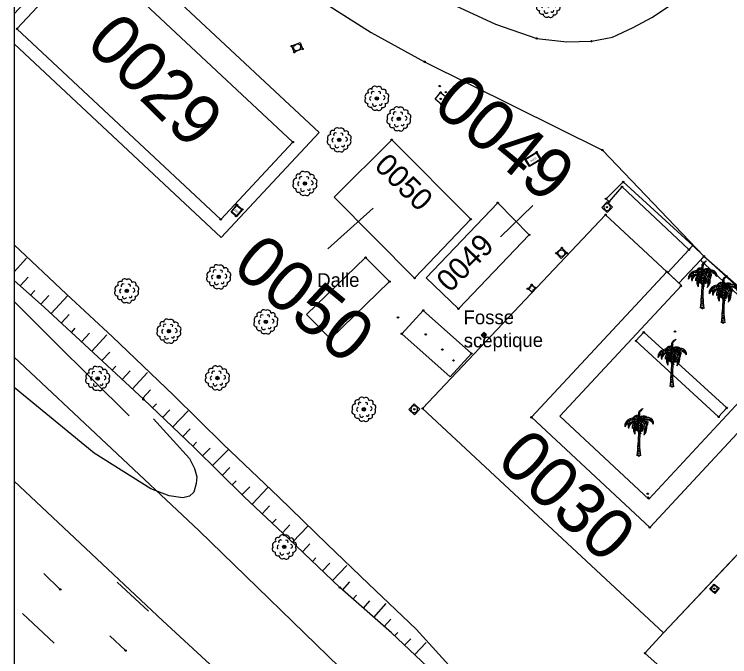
# Model space of a CAD drawing. Extents: x 344013 to 344423, y 298505 to 298795.
# Drawn here: x 344012.9 to 344064.6, y 298644.7 to 298691.1 of the extents above; entities that cross this region are included whole.
import ezdxf

# ---------------------------------------------------------------- set-up
doc = ezdxf.new("R2010")
doc.units = 0
for name, color, linetype in [('Default', 7, 'Continuous'), ('DH_CADRE -CARTOUCHE', 7, 'Continuous'), ('IMM_VOIRIE VOIE FERREE', 7, 'Continuous'), ('PC_CONCRETE', 7, 'Continuous'), ('PS_BOLT', 7, 'Continuous'), ('PS_CONST', 7, 'Continuous'), ('PS_HIDDEN', 7, 'Continuous'), ('PS_WELD', 7, 'Continuous'), ('RES_ELECTRICITE', 7, 'Continuous'), ('TOPO_COURBE NIVEAU', 7, 'Continuous'), ('TOPO_POINT', 7, 'Continuous'), ('TOPO_TALUS-TERRAIN NATUREL', 7, 'Continuous'), ('VOIRIE_BORDURE', 7, 'Continuous'), ('VOIRIE_ESPACE VERT', 7, 'Continuous')]:
    doc.layers.add(name, color=color, linetype=linetype)

# ---------------------------------------------------------------- blocks, each defined once
blk = doc.blocks.new('REG_INC')
at = {"layer": 'Default'}
for p, q in [((0, 1), (1, 1)), ((0, 0), (0, 1)), ((1, 1), (1, 0)), ((1, 0), (0, 0))]:
    blk.add_line(p, q, dxfattribs=at)
for centre, start, end in [((0.498, 0.5), 135.00554, 180.00554), ((0.5, 0.498), 90.00577, 135.00577), ((0.5, 0.5), 45.00687, 90.00687), ((0.499, 0.499), 0.00663, 45.00663), ((0.501, 0.5), 180.00663, 225.00663), ((0.499, 0.498), 225.00686, 270.00686), ((0.499, 0.5), 270.00577, 315.00577), ((0.501, 0.499), 315.00554, 0.00554)]:
    blk.add_arc(centre, 0.44, start, end, dxfattribs=at)
blk = doc.blocks.new('RES_ELECTRICITE')
at = {"layer": 'RES_ELECTRICITE'}
for points in [[(0, 0), (0, 1), (1, 1), (1, 0)], [(0.05, 0.05), (0.05, 0.95), (0.95, 0.95), (0.95, 0.05)]]:
    blk.add_lwpolyline(points, close=True, dxfattribs=at)
blk.add_text('EEC', height=0.2, dxfattribs=at).set_placement((0.237, 0.46))
blk = doc.blocks.new('POINT_DISPLAY')
at = {"layer": 'Default'}
blk.add_circle((0, 0), 0.05, dxfattribs=at)
blk = doc.blocks.new('COCO')
at = {"layer": 'Default'}
for p, q in [((-0.037, 1.06), (0.056, 1.071)), ((0.058, 1.14), (-0.03, 1.162)), ((-0.026, 1.226), (0.061, 1.212)), ((-0.062, 0.537), (0.046, 0.552)), ((0.047, 0.655), (-0.058, 0.642)), ((-0.046, 0.891), (0.052, 0.927)), ((0.054, 0.998), (-0.041, 0.985)), ((0.046, 0.033), (-0.076, 0.051)), ((-0.073, 0.17), (0.045, 0.209)), ((0.045, 0.292), (-0.07, 0.288)), ((-0.068, 0.371), (0.045, 0.374)), ((0.045, 0.47), (-0.065, 0.453))]:
    blk.add_line(p, q, dxfattribs=at)
for points in [[(0.029, 2.551), (-0.016, 2.896), (0.002, 3.125), (0.059, 3.241), (0.173, 3.348), (0.189, 3.356), (0.282, 3.415), (0.266, 3.373), (0.2, 3.318), (0.143, 3.247), (0.093, 3.2), (0.081, 3.165), (0.057, 3.133), (0.057, 3.099), (0.06, 3.037), (0.039, 2.989), (0.039, 2.944), (0.049, 2.877), (0.037, 2.841), (0.013, 2.736)], [(-0.636, 2.639), (-0.541, 2.608)], [(-0.487, 2.68), (-0.386, 2.65)], [(0.013, 2.736), (0.036, 2.813), (0.046, 2.746)], [(0.133, 2.608), (0.185, 2.634)], [(0.196, 2.687), (0.323, 2.715)], [(0.283, 2.765), (0.331, 2.786)], [(-0.746, 2.559), (-0.864, 2.483)], [(-0.77, 2.413), (-0.836, 2.333)], [(-0.607, 2.534), (-0.704, 2.443)], [(-0.421, 2.58), (-0.503, 2.523)], [(-0.183, 2.493), (-0.348, 2.417), (-0.401, 2.307), (-0.448, 2.203), (-0.471, 2.086), (-0.474, 2.023), (-0.466, 1.973), (-0.455, 2.054), (-0.451, 2.146), (-0.387, 2.292), (-0.351, 2.354), (-0.284, 2.404), (-0.233, 2.445), (-0.012, 2.495)], [(-0.256, 2.553), (-0.385, 2.508)], [(-0.276, 2.151), (-0.329, 2.086)], [(-0.203, 2.314), (-0.274, 2.258)], [(-0.23, 2.152), (-0.237, 2.043)], [(-0.161, 2.218), (-0.158, 2.122)], [(-0.04, 2.247), (-0.081, 2.179)], [(0.015, 2.414), (-0.056, 2.352)], [(0.022, 2.24), (0.043, 2.13)], [(0.081, 2.404), (0.106, 2.299)], [(0.385, 2.37), (0.469, 2.254)], [(0.473, 2.115), (0.509, 2.012)], [(-0.321, 1.997), (-0.364, 1.9)], [(-0.059, 2.024), (-0.083, 1.998)], [(-0.025, 2.032), (0.002, 1.954)], [(-0.055, 0.716), (0.048, 0.717), (0.049, 0.787), (-0.051, 0.795)]]:
    blk.add_lwpolyline(points, dxfattribs=at)
for centre, radius in [((-0.187, 1.897), 0.0384), ((-0.144, 1.978), 0.0616), ((-0.124, 1.896), 0.0376), ((-0.11, 1.84), 0.0471), ((0.134, 1.862), 0.0549), ((0.208, 1.822), 0.0626), ((0.254, 1.938), 0.0628)]:
    blk.add_circle(centre, radius, dxfattribs=at)
for centre, radius, start, end in [((-0.427, 2.113), 0.595, 43.6121, 181.4625), ((-0.38, 1.964), 0.648, 57.9192, 166.6201), ((-0.123, 2.59), 0.323, 122.3475, 158.7636), ((-0.199, 2.618), 0.238, 4.5218, 154.101), ((-0.252, 2.556), 0.231, 4.2441, 134.2103), ((-0.16, 2.647), 0.255, 21.0861, 122.3475), ((0.376, 2.508), 0.372, 113.7681, 175.3309), ((0.376, 2.508), 0.372, 113.7681, 175.3309), ((0.418, 2.527), 0.326, 97.1248, 183.9512), ((1.025, 2.053), 0.958, 126.6858, 153.1664), ((0.618, 2.316), 0.451, 356.1627, 159.0009), ((0.609, 2.187), 0.468, 12.1077, 148.3146), ((0.344, 2.407), 0.451, 69.0817, 104.862), ((-0.157, 2.027), 0.74, 51.2475, 54.5217), ((-1.005, 1.577), 1.786, 37.5668, 40.5156), ((-0.254, 2.28), 0.869, 28.4725, 37.0965), ((0.493, 2.767), 0.0679, 35.3205, 126.6858), ((-0.054, 2.379), 0.738, 25.8194, 35.3205), ((-0.291, 1.543), 0.918, 76.7389, 142.8025), ((-0.3, 2.12), 0.482, 151.1331, 199.5942), ((-0.196, 1.874), 0.565, 78.514, 171.3504), ((-0.32, 2.055), 0.433, 119.0834, 188.7621), ((0.362, 1.922), 0.754, 136.7113, 208.8221), ((0.551, 1.79), 0.879, 137.733, 194.3716), ((0.649, 1.599), 0.949, 145.5146, 182.4528), ((0.62, 2.159), 0.753, 153.0868, 230.1124), ((0.659, 2.068), 0.718, 142.3554, 222.2794), ((-0.007, 2.465), 0.0563, 81.7475, 144.3035), ((-0.189, 1.21), 1.324, 71.3715, 81.7475), ((0.294, 2.595), 0.256, 198.6765, 199.7627), ((0.963, 1.939), 0.9, 143.9866, 203.4288), ((0.544, 1.816), 0.474, 137.1953, 172.8987), ((0.308, 2.014), 0.226, 121.4297, 182.29), ((27.302, 0.106), 27.266, 175.4791, 176.5597), ((0.311, 2.152), 0.219, 141.856, 191.5175), ((0.242, 1.964), 0.147, 110.9727, 165.9756), ((0.404, 1.878), 0.354, 125.0585, 146.3893), ((0.398, 2.098), 0.301, 136.4569, 162.0685), ((0.357, 2.084), 0.244, 133.1184, 172.7534), ((-0.759, 1.958), 0.922, 344.8505, 15.8988), ((-0.404, 2.045), 0.619, 329.4666, 26.6793), ((-0.289, 2.11), 0.564, 317.8279, 12.3386), ((0.59, 2.015), 0.548, 29.5654, 139.3517), ((-0.543, 1.744), 0.96, 344.8781, 41.1461), ((-0.341, 1.9), 0.828, 46.9767, 50.1231), ((-0.341, 1.9), 0.828, 334.0687, 41.194), ((-0.157, 2.027), 0.74, 315.1472, 39.0239), ((-1.704, 1.849), 2.327, 7.5978, 16.3666), ((-0.254, 2.28), 0.869, 350.8883, 14.7063), ((-0.482, 2.552), 1.161, 339.3597, 356.5925), ((-85.428, 7.294), 85.622, 355.11326, 356.26352), ((-0.279, 1.637), 0.281, 2.1499, 36.6325), ((-0.265, 1.505), 0.316, 339.9997, 25.7228), ((0.199, 1.66), 0.176, 166.9443, 185.5966), ((0.372, 1.847), 0.277, 133.5956, 173.487), ((0.808, 1.542), 0.777, 142.2358, 156.28)]:
    blk.add_arc(centre, radius, start, end, dxfattribs=at)
blk.add_ellipse((27.425, 0.272), major_axis=(-27.371, 0.966), ratio=0.529859, start_param=6.255729, end_param=6.369141, dxfattribs=at)
blk = doc.blocks.new('ARB1')
at = {"layer": 'Default'}
blk.add_circle((0, 0), 0.122, dxfattribs=at)
for centre, radius, start, end in [((-0.471, 0.503), 0.183, 53.9554, 222.2066), ((-0.153, 0.664), 0.211, 43.6925, 183.5969), ((0.139, 0.613), 0.241, 358.4583, 125.1928), ((0.501, 0.468), 0.183, 325.1444, 131.0175), ((-0.613, 0.139), 0.241, 88.4583, 215.1928), ((-0.373, -0.024), 0.149, 103.7092, 242.3465), ((-0.276, 0.37), 0.134, 52.4396, 209.5496), ((0.164, 0.38), 0.112, 330.5895, 133.7127), ((0.458, 0.052), 0.137, 276.6214, 88.967), ((0.613, -0.139), 0.241, 268.4583, 35.1928), ((0.664, 0.153), 0.211, 313.6925, 93.5969), ((-0.664, -0.153), 0.211, 133.6925, 273.5969), ((-0.478, -0.443), 0.19, 155.2243, 300.9377), ((-0.163, -0.42), 0.148, 159.5371, 338.1663), ((0.271, -0.38), 0.112, 210.5895, 13.7127), ((0.448, -0.483), 0.188, 243.1323, 33.0297), ((-0.139, -0.613), 0.241, 178.4583, 305.1928), ((0.153, -0.664), 0.211, 223.6925, 3.5969)]:
    blk.add_arc(centre, radius, start, end, dxfattribs=at)

msp = doc.modelspace()

# ---------------------------------------------------------------- linework, layer by layer
at = {"layer": 'DH_CADRE -CARTOUCHE'}
for points in [[(344012.906, 298504.876), (344422.906, 298504.876), (344422.906, 298791.876), (344012.906, 298791.876)], [(344018.318, 298695.613), (344013.095, 298690.028), (344027.812, 298676.264), (344033.029, 298681.855)], [(344050.263, 298661.981), (344060.039, 298672.492), (344055.614, 298676.601), (344042.396, 298662.623), (344059.801, 298646.434), (344073.019, 298660.413), (344068.567, 298664.519), (344058.811, 298654.03)]]:
    msp.add_lwpolyline(points, close=True, dxfattribs=at)
at = {"layer": 'IMM_VOIRIE VOIE FERREE'}
for points in [[(344012.906, 298657.366), (344023.625, 298647.296), (344036.026, 298635.848), (344041.222, 298631.015), (344044.302, 298628.712), (344047.148, 298627.07), (344049.39, 298626.335), (344051.578, 298625.986), (344053.429, 298626.194), (344055.021, 298627.169), (344056.068, 298627.836), (344057.07, 298628.691)], [(344016.229, 298649.558), (344015.044, 298650.717)], [(344022.587, 298647.982), (344020.324, 298650.078)], [(344013.497, 298647.809), (344015.776, 298645.68)], [(344020.942, 298645.146), (344019.811, 298646.202)]]:
    msp.add_lwpolyline(points, dxfattribs=at)
at = {"layer": 'PS_BOLT'}
for points in [[(344012.906, 298688.945), (344027.856, 298674.963), (344034.929, 298682.543), (344018.872, 298697.524), (344012.906, 298691.117)], [(344056.894, 298678.972), (344055.647, 298677.763), (344055.865, 298677.55), (344056.813, 298678.629), (344061.637, 298674.087), (344061.918, 298674.376), (344056.894, 298678.972)], [(344042.396, 298662.623), (344055.614, 298676.601)], [(344061.918, 298674.376), (344062.722, 298673.608), (344062.468, 298673.339), (344060.919, 298671.674), (344060.107, 298672.429), (344061.918, 298674.376)], [(344057.812, 298667.504), (344063.774, 298662.011), (344064.365, 298662.656), (344058.376, 298668.119), (344057.812, 298667.504)]]:
    msp.add_lwpolyline(points, dxfattribs=at)
for points in [[(344043.302, 298684.953), (344043.703, 298685.435), (344044.152, 298685.062), (344043.762, 298684.57)], [(344038.281, 298673.518), (344040.014, 298671.784), (344035.75, 298667.659), (344034.017, 298669.394)], [(344062.722, 298673.608), (344062.468, 298673.339), (344069.15, 298667.15), (344069.435, 298667.48)], [(344045.931, 298666.585), (344042.441, 298669.7), (344040.893, 298668.015), (344044.383, 298664.9)], [(344059.801, 298646.434), (344058.46, 298644.956), (344062.597, 298641.269), (344072.85, 298652.396), (344068.937, 298656.096)]]:
    msp.add_lwpolyline(points, close=True, dxfattribs=at)
at = {"layer": 'PS_CONST'}
for p, q in [((344035.556, 298674.135), (344038.817, 298677.084)), ((344050.354, 298677.272), (344048.034, 298675.013))]:
    msp.add_line(p, q, dxfattribs=at)
at = {"layer": 'PS_HIDDEN'}
for points in [[(344036.003, 298677.876), (344040.167, 298682.02), (344045.881, 298676.278), (344041.823, 298672.027)], [(344044.99, 298669.815), (344042.645, 298672.058), (344047.827, 298677.475), (344050.1, 298675.156)], [(344060.039, 298672.492), (344050.263, 298661.981), (344058.811, 298654.03), (344068.567, 298664.519), (344067.505, 298665.507), (344058.737, 298656.08), (344052.312, 298662.055), (344061.101, 298671.505)]]:
    msp.add_lwpolyline(points, close=True, dxfattribs=at)
at = {"layer": 'PS_WELD'}
msp.add_lwpolyline([(344037.247, 298643.122), (344026.234, 298653.823), (344012.906, 298666.333)], dxfattribs=at)
at = {"layer": 'TOPO_COURBE NIVEAU'}
msp.add_lwpolyline([(344022.969, 298661.88), (344025.559, 298658.997), (344025.913, 298658.296), (344026.092, 298657.69), (344026.053, 298657.21), (344025.863, 298656.58), (344025.554, 298656.29), (344025.074, 298656.172), (344024.091, 298656.308), (344022.768, 298656.814), (344018.686, 298659.395), (344012.906, 298664.143)], dxfattribs=at)
at = {"layer": 'TOPO_TALUS-TERRAIN NATUREL'}
for p, q in [((344012.906, 298672.495), (344013.783, 298673.471)), ((344013.339, 298671.481), (344013.903, 298672.108)), ((344014.083, 298670.812), (344014.38, 298671.143)), ((344014.826, 298670.143), (344015.392, 298670.772)), ((344015.564, 298669.468), (344016.775, 298670.779)), ((344016.299, 298668.789), (344016.874, 298669.412)), ((344017.034, 298668.111), (344017.307, 298668.407)), ((344017.769, 298667.432), (344018.345, 298668.056)), ((344018.504, 298666.754), (344019.598, 298667.939)), ((344019.236, 298666.072), (344019.817, 298666.694)), ((344019.968, 298665.39), (344020.243, 298665.685)), ((344020.699, 298664.707), (344021.281, 298665.331)), ((344021.43, 298664.025), (344022.535, 298665.209)), ((344022.162, 298663.343), (344022.745, 298663.967)), ((344022.888, 298662.655), (344023.167, 298662.95)), ((344023.614, 298661.967), (344024.144, 298662.527)), ((344024.341, 298661.279), (344025.459, 298662.46)), ((344025.067, 298660.591), (344025.598, 298661.152)), ((344025.793, 298659.903), (344026.073, 298660.199)), ((344026.508, 298659.204), (344027.05, 298659.757)), ((344027.222, 298658.504), (344028.366, 298659.669)), ((344027.936, 298657.803), (344028.479, 298658.357)), ((344028.65, 298657.102), (344028.937, 298657.395)), ((344029.364, 298656.402), (344029.908, 298656.956)), ((344030.088, 298655.712), (344031.214, 298656.904)), ((344030.815, 298655.025), (344031.35, 298655.591)), ((344031.542, 298654.338), (344031.825, 298654.637)), ((344032.27, 298653.651), (344032.805, 298654.219)), ((344032.995, 298652.963), (344034.133, 298654.153)), ((344033.718, 298652.272), (344034.259, 298652.837)), ((344034.441, 298651.581), (344034.698, 298651.849)), ((344035.164, 298650.889), (344035.706, 298651.456)), ((344035.887, 298650.198), (344036.916, 298651.274)), ((344036.618, 298649.515), (344037.135, 298650.106)), ((344037.37, 298648.856), (344037.616, 298649.136)), ((344038.122, 298648.196), (344038.589, 298648.729)), ((344038.874, 298647.537), (344039.761, 298648.548)), ((344039.626, 298646.877), (344040.094, 298647.411)), ((344040.371, 298646.21), (344040.602, 298646.455)), ((344041.098, 298645.523), (344041.538, 298645.988)), ((344041.825, 298644.835), (344042.66, 298645.719))]:
    msp.add_line(p, q, dxfattribs=at)
for points in [[(344012.906, 298674.424), (344016.677, 298670.884), (344019.994, 298667.792), (344024.403, 298663.589), (344028.025, 298660.019), (344032.009, 298656.228), (344035.513, 298652.822), (344038.498, 298649.953), (344041.923, 298646.692), (344044.756, 298643.58), (344054.456, 298635.377)], [(344054.456, 298635.377), (344052.269, 298635.996), (344049.579, 298637.638), (344045.345, 298641.507), (344040.154, 298646.415), (344036.423, 298649.686), (344032.732, 298653.214), (344029.519, 298656.25), (344025.888, 298659.813), (344022.228, 298663.281), (344018.635, 298666.633), (344015.082, 298669.913), (344012.906, 298671.87)]]:
    msp.add_lwpolyline(points, dxfattribs=at)
at = {"layer": 'VOIRIE_BORDURE'}
for points in [[(344012.906, 298718.231), (344022.459, 298709.623), (344035.4, 298697.966), (344038.262, 298695.856), (344041.267, 298693.813), (344044.479, 298691.842), (344047.664, 298690.365), (344050.648, 298689.339), (344052.822, 298689.099), (344054.599, 298689.128), (344056.124, 298689.428), (344057.609, 298690.129), (344058.956, 298690.85), (344060.299, 298691.725), (344061.274, 298692.556), (344063.092, 298694.498), (344091.5, 298724.03), (344099.786, 298732.889), (344115.711, 298749.674), (344123.231, 298757.884), (344127.749, 298762.864), (344141.666, 298775.429), (344153.501, 298787.287)], [(344012.906, 298712.566), (344019.297, 298706.391), (344032.494, 298694.078), (344035.262, 298691.929), (344038.684, 298689.77), (344042.541, 298687.653), (344055.386, 298681.278), (344062.722, 298673.608), (344079.116, 298659.278), (344094.724, 298644.749), (344120.412, 298621.951), (344137.791, 298639.981)]]:
    msp.add_lwpolyline(points, dxfattribs=at)
at = {"layer": 'VOIRIE_ESPACE VERT'}
msp.add_lwpolyline([(344012.906, 298670.349), (344015.775, 298667.449), (344018.517, 298664.761), (344021.204, 298662.081)], dxfattribs=at)

# ---------------------------------------------------------------- block references
at = {"layer": 'PC_CONCRETE'}
for p, xscale, yscale, rotation in [((344033.125, 298688.339), 0.6530449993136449, 0.48712573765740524, 21.94433999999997), ((344055.719, 298677.546), 0.559179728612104, 0.55614695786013, -133.59555000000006), ((344052.052, 298673.828), 0.559435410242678, -0.51482037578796, 43.87266), ((344046.829, 298668.108), 0.260334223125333, -0.27775313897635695, -44.120166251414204), ((344041.787, 298662.958), 0.559179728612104, 0.55614695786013, -133.59555000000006), ((344063.145, 298649.58), 0.4815186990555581, 0.47498861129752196, -39.58739999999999)]:
    msp.add_blockref('REG_INC', p, dxfattribs=dict(at, xscale=xscale, yscale=yscale, rotation=rotation))
at = {"layer": 'RES_ELECTRICITE'}
for p, xscale, yscale, rotation in [((344050.63, 298681.131), 0.9750830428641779, 0.630212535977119, -148.96566), ((344029.377, 298676.991), 0.503977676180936, 0.665043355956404, 140.49315), ((344050.271, 298671.551), 0.36507635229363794, -0.395157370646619, -40.03803000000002)]:
    msp.add_blockref('RES_ELECTRICITE', p, dxfattribs=dict(at, xscale=xscale, yscale=yscale, rotation=rotation))
at = {"layer": 'TOPO_POINT'}
for p in [(344013.095, 298690.028), (344050.648, 298689.339), (344054.599, 298689.128), (344032.931, 298688.786), (344033.125, 298688.339), (344033.731, 298688.583), (344042.541, 298687.653), (344043.639, 298685.895), (344043.703, 298685.435), (344044.077, 298685.463), (344039.091, 298685.008), (344043.704, 298684.968), (344044.152, 298685.062), (344043.762, 298684.57), (344040.681, 298683.525), (344033.029, 298681.855), (344036.374, 298682.011), (344040.167, 298682.02), (344050.63, 298681.131), (344055.386, 298681.278), (344049.795, 298680.628), (344050.968, 298680.599), (344056.894, 298678.972), (344033.898, 298678.86), (344056.813, 298678.629), (344047.827, 298677.475), (344055.647, 298677.763), (344055.865, 298677.55), (344028.988, 298677.312), (344029.377, 298676.991), (344055.727, 298677.153), (344028.915, 298676.511), (344055.614, 298676.601), (344027.812, 298676.264), (344045.881, 298676.278), (344050.1, 298675.156), (344061.918, 298674.376), (344052.052, 298673.828), (344052.456, 298674.216), (344052.812, 298673.844), (344061.637, 298674.087), (344038.281, 298673.518), (344062.722, 298673.608), (344060.039, 298672.492), (344027.67, 298672.123), (344040.014, 298671.784), (344041.823, 298672.027), (344049.995, 298671.267), (344050.271, 298671.551), (344050.551, 298671.316), (344061.051, 298671.453), (344021.025, 298671.108), (344042.441, 298669.7), (344044.99, 298669.815), (344062.597, 298669.854), (344040.622, 298669.191), (344031.074, 298668.878), (344064.109, 298668.81), (344024.075, 298668.2), (344060.629, 298668.176), (344035.75, 298667.659), (344040.893, 298668.015), (344042.626, 298667.97), (344046.826, 298667.918), (344058.376, 298668.119), (344045.88, 298667.13), (344057.812, 298667.504), (344043.824, 298666.872), (344045.931, 298666.585), (344044.631, 298666.091), (344018.928, 298664.786), (344027.574, 298664.82), (344060.403, 298664.197), (344022.228, 298663.281), (344038.154, 298662.56), (344041.796, 298662.564), (344042.396, 298662.623), (344064.365, 298662.656), (344050.263, 298661.981), (344063.774, 298662.011), (344058.017, 298659.209), (344058.657, 298656.463), (344058.674, 298656.183), (344058.811, 298654.03), (344032.408, 298652.622), (344016.229, 298649.558), (344036.423, 298649.686), (344063.481, 298649.609), (344020.942, 298645.146), (344058.46, 298644.956)]:
    msp.add_blockref('POINT_DISPLAY', p, dxfattribs=at)
at = {"layer": 'VOIRIE_ESPACE VERT'}
for name, p in [('ARB1', (344051.49, 298691.717)), ('ARB1', (344039.091, 298685.008)), ('ARB1', (344040.681, 298683.525)), ('ARB1', (344036.374, 298682.011)), ('ARB1', (344033.898, 298678.86)), ('ARB1', (344027.67, 298672.123)), ('COCO', (344062.597, 298669.854)), ('ARB1', (344021.025, 298671.108)), ('COCO', (344064.109, 298668.81)), ('ARB1', (344031.074, 298668.878)), ('ARB1', (344024.075, 298668.2)), ('COCO', (344060.403, 298664.197)), ('ARB1', (344018.928, 298664.786)), ('ARB1', (344027.574, 298664.82)), ('ARB1', (344038.154, 298662.56)), ('COCO', (344058.017, 298659.209)), ('ARB1', (344032.408, 298652.622))]:
    msp.add_blockref(name, p, dxfattribs=at)

# ---------------------------------------------------------------- texts
at = {"layer": 'PS_CONST'}
for s, height, rotation, p in [('0029', 3.662, 315.3665, (344017.955, 298688.867)), ('0049', 3.662, 320.3665, (344042.992, 298684.271)), ('0050', 1.5764, 315.4316, (344038.833, 298680.051)), ('0050', 3.662, 320.3665, (344028.513, 298672.644)), ('0049', 1.5764, 45.4316, (344044.366, 298670.928)), ('Dalle', 1.0003, 0.3665, (344034.789, 298671.385)), ('Fosse', 1.0003, 0.3665, (344045.362, 298668.694)), ('sceptique', 1.0003, 0.3665, (344045.373, 298667.027)), ('0030', 3.662, 317.2565, (344047.604, 298658.724))]:
    msp.add_text(s, height=height, rotation=rotation, dxfattribs=at).set_placement(p)

doc.saveas('drawing.dxf')
